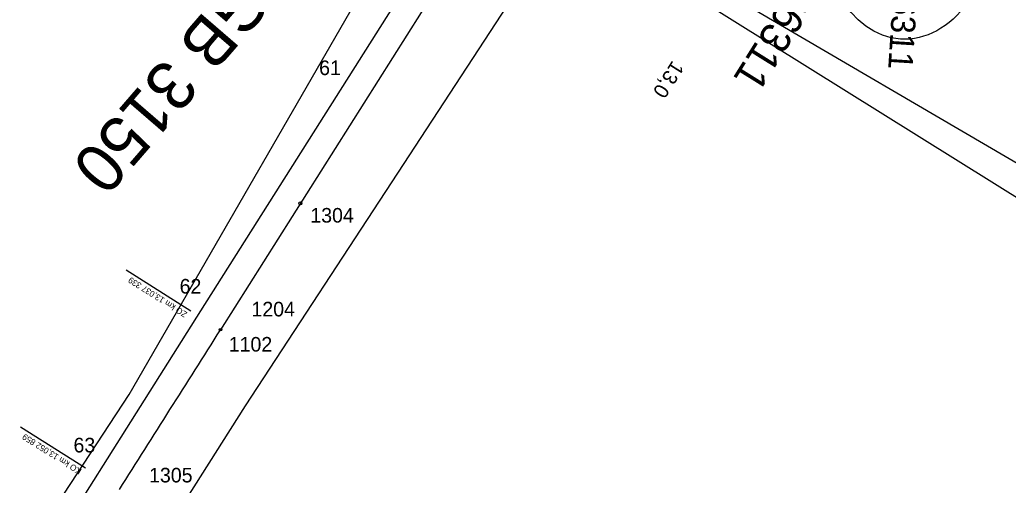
# Model space of a CAD drawing. Extents: x -743546 to -74, y -1128126 to -103.
# Drawn here: x -743214 to -743132.9, y -1127147.7 to -1127109.4 of the extents above; entities that cross this region are included whole.
import ezdxf

# ---------------------------------------------------------------- set-up
doc = ezdxf.new("R2010")
doc.units = 0
for name, color, linetype in [('_Násyp', 7, 'Continuous'), ('_Zabezpečovací zařízení_trasa', 7, 'Continuous'), ('bublina_fialová_čára_tenká', 7, 'Continuous'), ('bublina_fialová_čára_tučná', 7, 'Continuous'), ('křížky', 7, 'Continuous'), ('Nový stav', 7, 'Continuous'), ('OSA_POP', 7, 'Continuous'), ('POP_OBLOUK', 7, 'Continuous'), ('SMER_VYS_VYROVNANI', 7, 'Continuous'), ('Vrstva 53', 7, 'Continuous'), ('Vrstva 60', 7, 'Continuous'), ('ŽBP', 7, 'Continuous')]:
    doc.layers.add(name, color=color, linetype=linetype)

# ---------------------------------------------------------------- blocks, each defined once
blk = doc.blocks.new('AeccTickCircle')
blk.add_circle((0, 0), 0.5)
blk = doc.blocks.new('POINT_DISPLAY')
blk.add_line((0, 0), (0, 0))

msp = doc.modelspace()

# ---------------------------------------------------------------- linework, layer by layer
at = {"layer": '_Zabezpečovací zařízení_trasa'}
msp.add_lwpolyline([(-743049.28, -1126895.951), (-743072.487, -1126932.751), (-743098.647, -1126974.146), (-743125.94, -1127017.384), (-743152.604, -1127059.608), (-743175.023, -1127095.116), (-743199.163, -1127133.346), (-743215.971, -1127159.941), (-743232.818, -1127186.515), (-743247.456, -1127209.811), (-743254.52, -1127221.639), (-743261.299, -1127233.691), (-743264.155, -1127239.195), (-743264.862, -1127241.108), (-743267.337, -1127245.816)], dxfattribs=at)
at = {"layer": 'bublina_fialová_čára_tenká'}
for p, q in [((-743129.509, -1127122.8), (-743175.485, -1127095.847)), ((-743109.419, -1127138.306), (-743174.121, -1127097.814))]:
    msp.add_line(p, q, dxfattribs=at)
at = {"layer": 'bublina_fialová_čára_tučná'}
msp.add_ellipse((-743140.999, -1127099.794), major_axis=(0.716, 11.227), ratio=0.666667, dxfattribs=at)
at = {"layer": 'OSA_POP'}
for p, q in [((-743199.951, -1127133.355), (-743205.278, -1127129.992)), ((-743199.951, -1127133.355), (-743205.278, -1127129.992)), ((-743208.615, -1127146.251), (-743213.939, -1127142.882)), ((-743208.615, -1127146.251), (-743213.939, -1127142.882))]:
    msp.add_line(p, q, dxfattribs=at)
at = {"layer": 'SMER_VYS_VYROVNANI'}
msp.add_lwpolyline([(-743178.712, -1127105.086), (-743197.526, -1127134.888)], dxfattribs=at)
msp.add_arc((-755881.535, -1119127.648), 14999.999, 327.6770641, 327.736346, dxfattribs=at)
at = {"layer": 'Vrstva 53'}
for points in [[(-743280.26, -1127263.68), (-743264.54, -1127233.06), (-743246.95, -1127204.21), (-743235.54, -1127186.77), (-743205.03, -1127140.21), (-743183.34, -1127102.57)], [(-743183.34, -1127102.57), (-743171.62, -1127104.6), (-743183.01, -1127122.02), (-743195.51, -1127141.13), (-743203.92, -1127154.43), (-743215.95, -1127172.74), (-743210.36, -1127174.02), (-743237.28, -1127205.49), (-743245.75, -1127220.06), (-743259.48, -1127245.93)]]:
    msp.add_lwpolyline(points, dxfattribs=at)
at = {"layer": 'Vrstva 60'}
for p, q in [((-743187.093, -1127114.231), (-743187.093, -1127114.231)), ((-743190.939, -1127124.455), (-743190.939, -1127124.455)), ((-743195.804, -1127132.162), (-743195.804, -1127132.162)), ((-743199.163, -1127133.346), (-743199.163, -1127133.346)), ((-743197.526, -1127134.888), (-743197.526, -1127134.888)), ((-743204.289, -1127145.592), (-743204.289, -1127145.592)), ((-743207.567, -1127146.644), (-743207.567, -1127146.644))]:
    msp.add_line(p, q, dxfattribs=at)

# ---------------------------------------------------------------- block references
at = {"layer": 'křížky', "xscale": 10, "yscale": 10, "rotation": 61.14491455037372}
for p in [(-743187.093, -1127114.231), (-743190.939, -1127124.455), (-743195.804, -1127132.162), (-743199.163, -1127133.346), (-743197.526, -1127134.888), (-743204.289, -1127145.592), (-743207.567, -1127146.644)]:
    msp.add_blockref('POINT_DISPLAY', p, dxfattribs=at)
at = {"layer": 'OSA_POP', "xscale": 0.2, "yscale": 0.19999999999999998, "rotation": -122.26365395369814}
msp.add_blockref('AeccTickCircle', (-743197.526, -1127134.888), dxfattribs=at)
msp.add_blockref('AeccTickCircle', (-743197.526, -1127134.888), dxfattribs=at)
at = {"layer": 'POP_OBLOUK', "xscale": 0.24999999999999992, "yscale": 0.24999999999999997, "rotation": 57.71650678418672}
msp.add_blockref('AeccTickCircle', (-743190.973, -1127124.502), dxfattribs=at)

# ---------------------------------------------------------------- texts
at = {"layer": '_Násyp'}
msp.add_text('PŘEJEZD P6311', height=2, rotation=266.35277, dxfattribs=at).set_placement((-743141.419, -1127092.843))
at = {"layer": 'Nový stav'}
msp.add_text('P6311', height=2.5, rotation=238, dxfattribs=at).set_placement((-743150.378, -1127106.013))
at = {"layer": 'OSA_POP'}
for s, height, rotation, p in [('13,0', 1.2, 237.73635, (-743160.427, -1127112.71)), ('13,0', 1.2, 237.73635, (-743160.427, -1127112.71)), ('ZO km 13,037 339', 0.5, 147.73635, (-743200.211, -1127133.486)), ('ZO km 13,037 339', 0.5, 147.73635, (-743200.211, -1127133.486)), ('KO km 13,052 859', 0.5, 147.67706, (-743208.875, -1127146.381)), ('KO km 13,052 859', 0.5, 147.67706, (-743208.875, -1127146.381))]:
    msp.add_text(s, height=height, rotation=rotation, dxfattribs=at).set_placement(p)
at = {"layer": 'Vrstva 60'}
for s, p in [('61', (-743189.432, -1127113.973)), ('1304', (-743190.155, -1127126.088)), ('62', (-743200.879, -1127131.914)), ('1204', (-743194.985, -1127133.792)), ('1102', (-743196.851, -1127136.682)), ('63', (-743209.59, -1127144.961)), ('1305', (-743203.388, -1127147.427))]:
    msp.add_text(s, height=1.2, dxfattribs=at).set_placement(p)
at = {"layer": 'ŽBP'}
msp.add_text('ZGB 3150', height=3.9996, rotation=229.17476, dxfattribs=at).set_placement((-743193.967, -1127102.98))

doc.saveas('drawing.dxf')
